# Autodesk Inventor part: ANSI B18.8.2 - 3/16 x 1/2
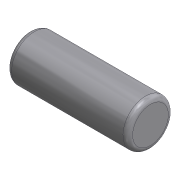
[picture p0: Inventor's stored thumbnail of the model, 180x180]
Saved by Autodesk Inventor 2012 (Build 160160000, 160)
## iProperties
Created: 2000-07
Part Number: ANSI B18.8.2 - 3/16 x 1/2
Material: Stainless Steel, Austenitic
Description: Pin - Hardened  Dowel 3/16 x 1/2
Document SubType Name: Standard Catalog Part
Standard: ANSI B18.8.2 - 3/16 x 1/2
Designer: Ron
Mass: 1.80401 g
Surface Area: 2.18889 cm^2
Volume: 0.224659 cm^3
Density: 8.03 g/cm^3
Control State: 0
Master: False
Checked Out: False
Shininess: 60.0
Length Units: 11272
Angle Units: 11279
Time Units: 11290
Mass Units: 11286
Length Display Precision: 3
Angle Display Precision: 2
Density: 0.0
Volumn: 0.0
Area: 0.0
PropertySet Name: Model Information
Author: Ron
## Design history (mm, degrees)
node "Base1"
body "Solid1"
